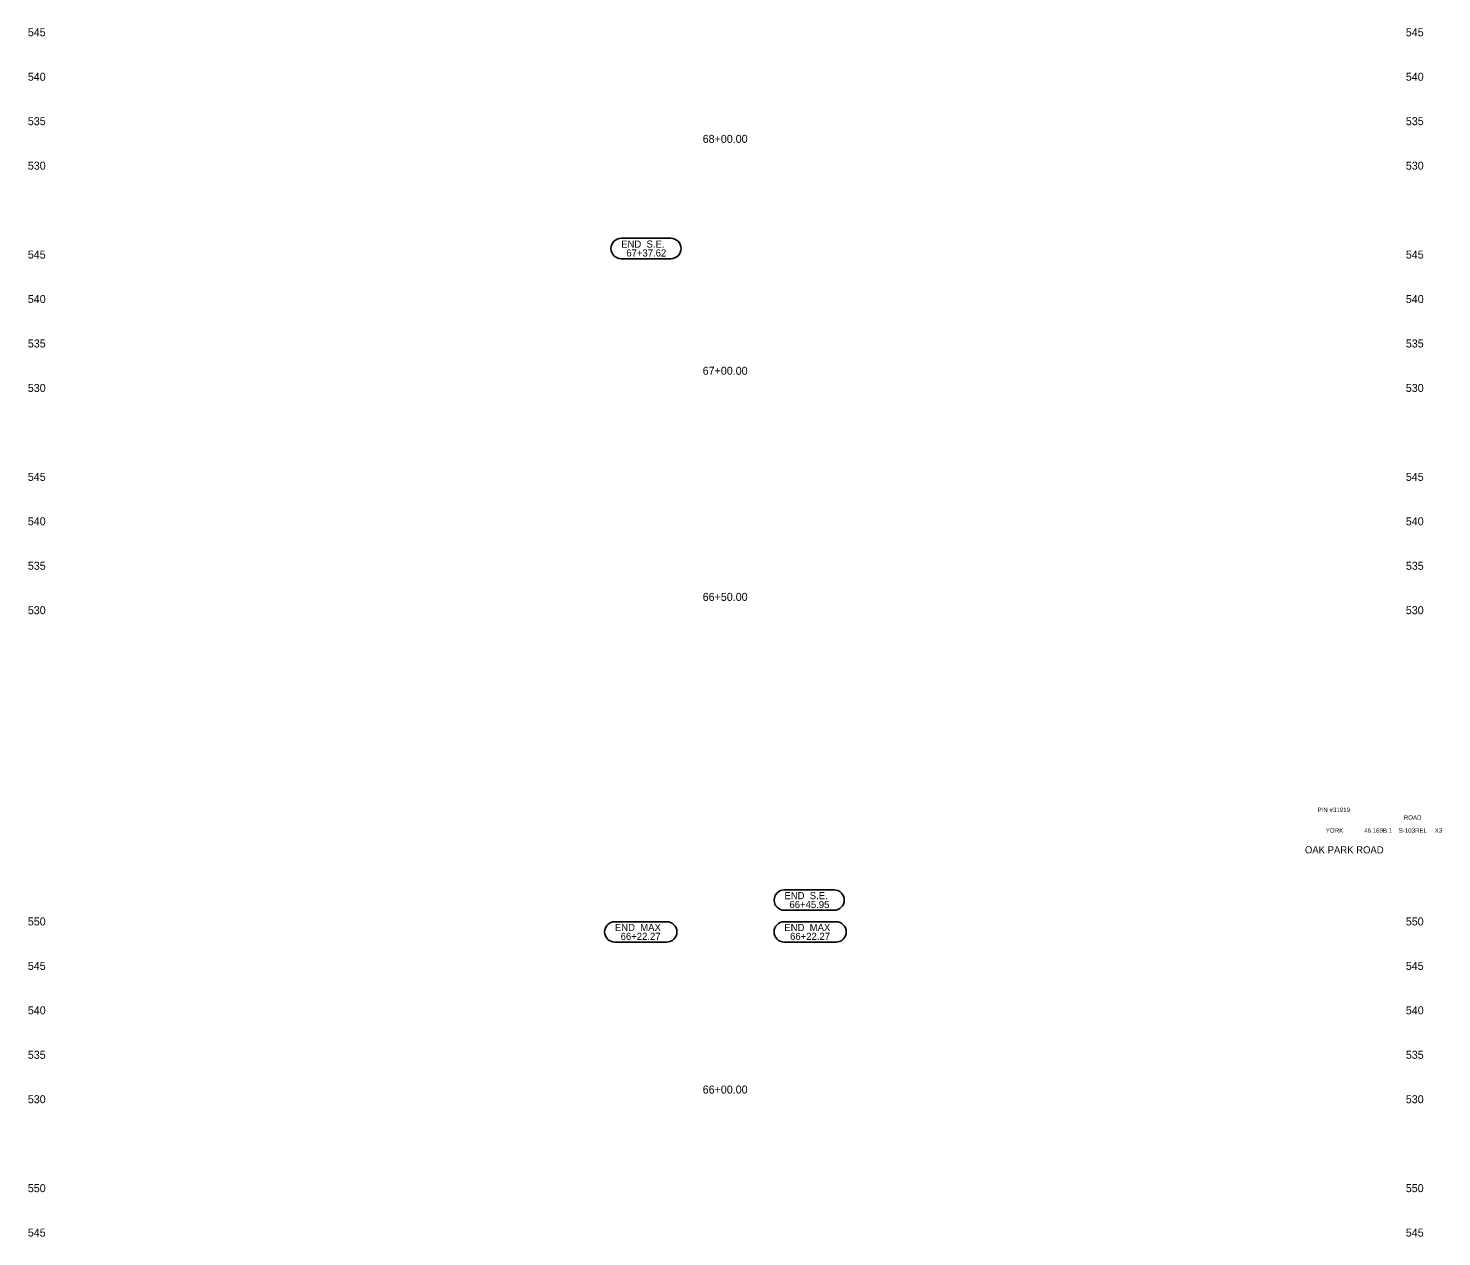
# Model space of a CAD drawing. Extents: x 1001 to 1160, y 1003 to 1563.
# Drawn here: x 1001.5 to 1160.5, y 1285 to 1420.9 of the extents above; entities that cross this region are included whole.
import ezdxf

# ---------------------------------------------------------------- set-up
doc = ezdxf.new("R2010")
doc.units = 0
for name, color, linetype in [('Level 25', 7, 'Continuous'), ('Level 41', 7, 'Continuous'), ('Level 56', 7, 'Continuous')]:
    doc.layers.add(name, color=color, linetype=linetype)

msp = doc.modelspace()

# ---------------------------------------------------------------- linework, layer by layer
at = {"layer": 'Level 41'}
for p, q in [((1073.78, 1397.28), (1068.19, 1397.28)), ((1068.19, 1394.98), (1073.78, 1394.98)), ((1092.13, 1324), (1086.55, 1324)), ((1086.55, 1321.7), (1092.13, 1321.7)), ((1073.31, 1320.42), (1067.48, 1320.42)), ((1092.36, 1320.42), (1086.54, 1320.42)), ((1067.48, 1318.12), (1073.31, 1318.12)), ((1086.54, 1318.12), (1092.36, 1318.12))]:
    msp.add_line(p, q, dxfattribs=at)
for centre, start, end in [((1068.19, 1396.13), 90, 270), ((1073.78, 1396.13), 270, 90), ((1086.55, 1322.85), 90, 270), ((1092.13, 1322.85), 270, 90), ((1067.48, 1319.27), 90, 270), ((1073.31, 1319.27), 270, 90), ((1086.54, 1319.27), 90, 270), ((1092.36, 1319.27), 270, 90)]:
    msp.add_arc(centre, 1.15, start, end, dxfattribs=at)

# ---------------------------------------------------------------- texts
at = {"layer": 'Level 25'}
for s, p in [('68+00.00', (1077.36, 1408.01)), ('67+00.00', (1077.36, 1381.93)), ('66+50.00', (1077.36, 1356.5)), ('66+00.00', (1077.36, 1301.09))]:
    msp.add_text(s, height=0.9, dxfattribs=at).set_placement(p)
at = {"layer": 'Level 41'}
for s, height, p in [('END  S.E.', 0.8, (1068.19, 1396.23)), ('67+37.62', 0.8, (1068.77, 1395.23)), ('PIN #31919', 0.5, (1146.52, 1332.75)), ('ROAD', 0.5, (1156.22, 1331.88)), ('YORK', 0.5, (1147.45, 1330.43)), ('46.169B.1', 0.5, (1151.76, 1330.43)), ('S-103REL', 0.5, (1155.64, 1330.43)), ('X3', 0.5, (1159.7, 1330.43)), ('OAK PARK ROAD', 0.8, (1145.1, 1328.1)), ('END  S.E.', 0.8, (1086.55, 1322.95)), ('66+45.95', 0.8, (1087.12, 1321.95)), ('END  MAX', 0.8, (1067.48, 1319.37)), ('END  MAX', 0.8, (1086.54, 1319.37)), ('66+22.27', 0.8, (1068.13, 1318.37)), ('66+22.27', 0.8, (1087.19, 1318.37))]:
    msp.add_text(s, height=height, dxfattribs=at).set_placement(p)
at = {"layer": 'Level 56'}
for s, p in [('545', (1001.45, 1420)), ('545', (1156.45, 1420)), ('540', (1001.45, 1415)), ('540', (1156.45, 1415)), ('535', (1001.45, 1410)), ('535', (1156.45, 1410)), ('530', (1001.45, 1405)), ('530', (1156.45, 1405)), ('545', (1001.45, 1395)), ('545', (1156.45, 1395)), ('540', (1001.45, 1390)), ('540', (1156.45, 1390)), ('535', (1001.45, 1385)), ('535', (1156.45, 1385)), ('530', (1001.45, 1380)), ('530', (1156.45, 1380)), ('545', (1001.45, 1370)), ('545', (1156.45, 1370)), ('540', (1001.45, 1365)), ('540', (1156.45, 1365)), ('535', (1001.45, 1360)), ('535', (1156.45, 1360)), ('530', (1001.45, 1355)), ('530', (1156.45, 1355)), ('550', (1001.45, 1320)), ('550', (1156.45, 1320)), ('545', (1001.45, 1315)), ('545', (1156.45, 1315)), ('540', (1001.45, 1310)), ('540', (1156.45, 1310)), ('535', (1001.45, 1305)), ('535', (1156.45, 1305)), ('530', (1001.45, 1300)), ('530', (1156.45, 1300)), ('550', (1001.45, 1290)), ('550', (1156.45, 1290)), ('545', (1001.45, 1285)), ('545', (1156.45, 1285))]:
    msp.add_text(s, height=0.9, dxfattribs=at).set_placement(p)

doc.saveas('drawing.dxf')
